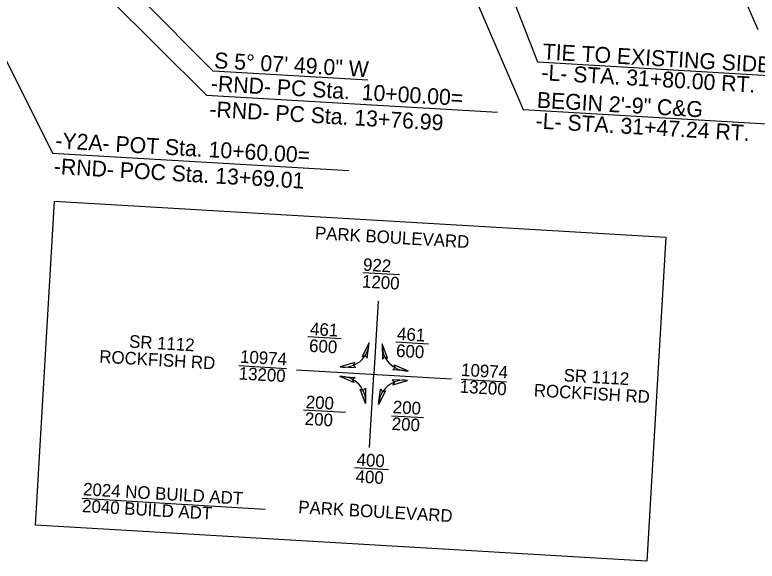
# Model space of a CAD drawing. Extents: x 2010838 to 2015151, y 441905 to 447792.
# Drawn here: x 2013251.3 to 2013578.4, y 444509 to 444749.8 of the extents above; entities that cross this region are included whole.
import ezdxf

# ---------------------------------------------------------------- set-up
doc = ezdxf.new("R2010")
doc.units = 0
for name, color, linetype in [('1-BUFFER', 7, 'Continuous'), ('Cont-2-Lidar', 7, 'Continuous'), ('Default_10ft_LIDAR_Contou', 7, 'Continuous'), ('S-Existing Minor', 7, 'Continuous')]:
    doc.layers.add(name, color=color, linetype=linetype)

msp = doc.modelspace()

# ---------------------------------------------------------------- linework, layer by layer
at = {"layer": '1-BUFFER'}
for p, q in [((2013404.65, 444636.23), (2013420.82, 444635.28)), ((2013411.41, 444623.56), (2013409.51, 444591.34)), ((2013380.42, 444607.95), (2013395.16, 444607.08)), ((2013419.2, 444605.67), (2013433.53, 444604.82)), ((2013349.99, 444595.17), (2013370.95, 444593.94)), ((2013375.35, 444593.35), (2013443.66, 444589.33)), ((2013407.61, 444559.11), (2013409.51, 444591.34)), ((2013447.98, 444589.17), (2013467.89, 444588)), ((2013378.52, 444575.72), (2013397, 444574.63)), ((2013417.28, 444573.1), (2013431.44, 444572.27)), ((2013400.94, 444550.31), (2013415.98, 444549.42)), ((2013280.81, 444536.71), (2013361.61, 444531.94))]:
    msp.add_line(p, q, dxfattribs=at)
for points in [[(2013268.78, 444667.7), (2013538.2, 444651.82), (2013529.78, 444508.96), (2013260.36, 444524.84)], [(2013406.53, 444598.45), (2013407.45, 444605.15), (2013404.29, 444599.12), (2013405.68, 444599.57)], [(2013415.53, 444598.47), (2013413.17, 444604.81), (2013413.24, 444598.01), (2013414.25, 444599.06)], [(2013401.17, 444596.58), (2013394.7, 444594.61), (2013401.5, 444594.27), (2013400.51, 444595.34)], [(2013418.41, 444595.58), (2013424.59, 444592.85), (2013417.81, 444593.33), (2013418.92, 444594.27)], [(2013400.65, 444587.68), (2013394.45, 444590.39), (2013401.24, 444589.93), (2013400.13, 444588.99)], [(2013417.88, 444586.65), (2013424.34, 444588.63), (2013417.55, 444588.96), (2013418.54, 444587.89)], [(2013405.75, 444585.19), (2013405.87, 444578.43), (2013403.45, 444584.79), (2013404.77, 444584.18)], [(2013414.68, 444584.11), (2013411.6, 444578.1), (2013412.47, 444584.84), (2013413.35, 444583.68)]]:
    msp.add_lwpolyline(points, close=True, dxfattribs=at)
for centre, start, end in [((2013396.35, 444605.6), 261.4901, 357.6705), ((2013424.25, 444603.96), 175.5823, 271.7627), ((2013394.8, 444579.29), 355.5885, 91.7689), ((2013422.7, 444577.65), 81.4962, 177.6766)]:
    msp.add_arc(centre, 11.11, start, end, dxfattribs=at)
at = {"layer": 'Default_10ft_LIDAR_Contou'}
for p, q in [((2013490.45, 444945.53), (2013578.8, 444743.32)), ((2013184.86, 444880.3), (2013338.65, 444724.98)), ((2013182.91, 444858.64), (2013267.89, 444688.86)), ((2013190.89, 444858.45), (2013335.72, 444714.48)), ((2013406.77, 444720.97), (2013338.65, 444724.98)), ((2013335.72, 444714.48), (2013463.94, 444706.92)), ((2013267.89, 444688.86), (2013398.49, 444681.16))]:
    msp.add_line(p, q, dxfattribs=at)
at = {"layer": 'S-Existing Minor'}
for p, q in [((2013383.77, 444920.55), (2013475.24, 444708.05)), ((2013422.83, 444881.92), (2013481.56, 444729.13)), ((2013481.56, 444729.13), (2013615.18, 444721.26)), ((2013481.56, 444729.13), (2013615.18, 444721.26)), ((2013475.24, 444708.05), (2013582.73, 444701.71))]:
    msp.add_line(p, q, dxfattribs=at)

# ---------------------------------------------------------------- texts
at = {"layer": '1-BUFFER'}
for s, height, p in [('PARK BOULEVARD', 5.5531, (2013383.43, 444650.98)), ('922', 5.553, (2013404.6, 444637.02)), ('1200', 5.553, (2013404.16, 444629.63)), ('461', 5.553, (2013381.26, 444608.68)), ('461', 5.553, (2013419.61, 444606.48)), ('SR 1112', 5.553, (2013301.49, 444603.15)), ('600', 5.553, (2013380.83, 444601.29)), ('ROCKFISH RD', 5.5531, (2013288.37, 444596.5)), ('10974', 5.553, (2013350.41, 444596.45)), ('600', 5.553, (2013419.17, 444599.08)), ('10974', 5.553, (2013447.83, 444590.65)), ('13200', 5.553, (2013349.82, 444589.07)), ('SR 1112', 5.553, (2013493.02, 444588.26)), ('13200', 5.553, (2013447.24, 444583.26)), ('ROCKFISH RD', 5.5531, (2013479.9, 444581.62)), ('200', 5.553, (2013379.36, 444576.46)), ('200', 5.553, (2013417.71, 444574.25)), ('200', 5.553, (2013378.93, 444569.07)), ('200', 5.553, (2013417.27, 444566.86)), ('400', 5.553, (2013401.78, 444551.05)), ('400', 5.553, (2013401.34, 444543.66)), ('2024 NO BUILD ADT', 5.5531, (2013281.23, 444538.02)), ('2040 BUILD ADT', 5.5531, (2013280.8, 444530.62)), ('PARK BOULEVARD', 5.5531, (2013376.08, 444530.14))]:
    msp.add_text(s, height=height, rotation=356.6264, dxfattribs=at).set_placement(p)
at = {"layer": 'Cont-2-Lidar'}
msp.add_text('S 5%%d 07\' 49.0" W', height=7, rotation=356.6264, dxfattribs=at).set_placement((2013338.95, 444726.33))
at = {"layer": 'Default_10ft_LIDAR_Contou'}
for s, p in [('-RND- PC Sta.  10+00.00=', (2013337.52, 444716.22)), ('-RND- PC Sta. 13+76.99', (2013336.85, 444704.87)), ('-Y2A- POT Sta. 10+60.00=', (2013268.97, 444691.04)), ('-RND- POC Sta. 13+69.01', (2013268.3, 444679.68))]:
    msp.add_text(s, height=7, rotation=356.6264, dxfattribs=at).set_placement(p)
at = {"layer": 'S-Existing Minor'}
for s, p in [('TIE TO EXISTING SIDEWALK ', (2013483.74, 444730.22)), ('TIE TO EXISTING SIDEWALK ', (2013483.74, 444730.22)), ('-L- STA. 31+80.00 RT.', (2013483.2, 444721.06)), ('-L- STA. 31+80.00 RT.', (2013483.2, 444721.06)), ('BEGIN 2\'-9" C&G ', (2013481.2, 444708.91)), ('-L- STA. 31+47.24 RT.', (2013480.66, 444699.75))]:
    msp.add_text(s, height=7, rotation=356.6264, dxfattribs=at).set_placement(p)

doc.saveas('drawing.dxf')
